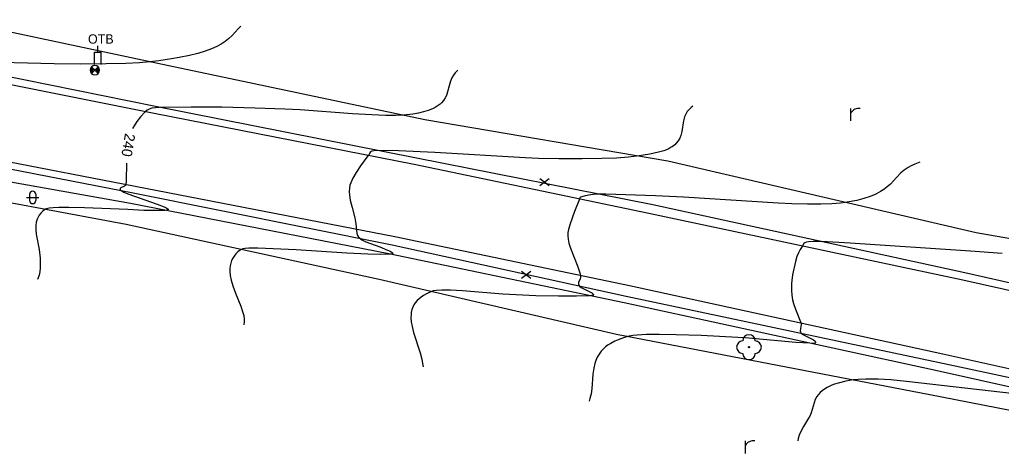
# Model space of a CAD drawing. Extents: x -593772 to -592667, y -1183541 to -1183371.
# Drawn here: x -593321.2 to -593242.3, y -1183436.1 to -1183401.2 of the extents above; entities that cross this region are included whole.
import ezdxf

# ---------------------------------------------------------------- set-up
doc = ezdxf.new("R2010")
doc.units = 0
for name, color, linetype in [('bez obruby', 7, 'Continuous'), ('hlavni vrstevnice', 7, 'Continuous'), ('popis ploch', 7, 'Continuous'), ('Statni bodove pole', 7, 'Continuous'), ('svisle dopravni znaceni', 7, 'Continuous'), ('terenni hrany', 7, 'Continuous'), ('vrstevnice', 7, 'Continuous'), ('zelen', 7, 'Continuous')]:
    doc.layers.add(name, color=color, linetype=linetype)

msp = doc.modelspace()

# ---------------------------------------------------------------- linework, layer by layer
at = {"layer": 'bez obruby'}
for p, q in [((-593310.39, -1183408.78), (-593327.76, -1183405.29)), ((-593289.5, -1183412.86), (-593310.39, -1183408.78)), ((-593311.94, -1183414.64), (-593328.65, -1183411.38)), ((-593270.63, -1183416.8), (-593289.5, -1183412.86)), ((-593291.05, -1183418.69), (-593311.94, -1183414.64)), ((-593245.4, -1183422.16), (-593270.63, -1183416.8)), ((-593272.2, -1183422.61), (-593291.05, -1183418.69)), ((-593247, -1183428.11), (-593272.2, -1183422.61)), ((-593226.44, -1183426.4), (-593245.4, -1183422.16)), ((-593227.63, -1183432.42), (-593247, -1183428.11))]:
    msp.add_line(p, q, dxfattribs=at)
at = {"layer": 'hlavni vrstevnice'}
for points in [[(-593285.982, -1183405.292), (-593286.206, -1183405.515), (-593286.352, -1183405.702), (-593286.466, -1183405.902), (-593286.579, -1183406.177), (-593286.681, -1183406.534), (-593286.808, -1183407.037), (-593286.906, -1183407.318), (-593287.004, -1183407.52), (-593287.133, -1183407.717), (-593287.291, -1183407.901), (-593287.42, -1183408.018), (-593287.645, -1183408.18), (-593287.822, -1183408.284), (-593288.022, -1183408.382), (-593288.382, -1183408.522), (-593288.748, -1183408.635), (-593289.158, -1183408.732), (-593289.621, -1183408.812), (-593290.362, -1183408.893), (-593290.981, -1183408.924), (-593291.776, -1183408.925), (-593292.914, -1183408.887), (-593294.455, -1183408.796), (-593298.67, -1183408.481), (-593299.901, -1183408.411), (-593302.272, -1183408.329), (-593304.97, -1183408.272), (-593307.424, -1183408.255), (-593309.976, -1183408.284), (-593310.301, -1183408.304), (-593310.598, -1183408.348), (-593310.808, -1183408.411), (-593310.953, -1183408.489), (-593311.146, -1183408.662), (-593311.487, -1183409.03), (-593311.787, -1183409.405), (-593312.017, -1183409.751), (-593312.141, -1183409.978)], [(-593312.62, -1183412.761), (-593312.649, -1183414.159), (-593312.669, -1183414.504), (-593312.698, -1183414.553), (-593312.797, -1183414.616), (-593313.076, -1183414.741), (-593313.133, -1183414.794), (-593313.144, -1183414.838), (-593313.121, -1183414.889), (-593313.055, -1183414.949), (-593312.841, -1183415.077), (-593312.524, -1183415.211), (-593310.152, -1183416.043), (-593309.597, -1183416.265), (-593309.391, -1183416.369), (-593309.307, -1183416.431), (-593309.282, -1183416.467), (-593309.285, -1183416.496), (-593309.316, -1183416.52), (-593309.41, -1183416.544), (-593309.511, -1183416.553), (-593310.49, -1183416.573), (-593311.236, -1183416.551), (-593312.526, -1183416.476), (-593315.997, -1183416.337), (-593317.267, -1183416.31), (-593318.053, -1183416.316), (-593318.531, -1183416.34), (-593318.842, -1183416.375), (-593319.046, -1183416.419), (-593319.156, -1183416.463), (-593319.376, -1183416.636), (-593319.515, -1183416.778), (-593319.63, -1183416.927), (-593319.724, -1183417.084), (-593319.798, -1183417.247), (-593319.873, -1183417.503), (-593319.909, -1183417.776), (-593319.912, -1183418.064), (-593319.873, -1183418.462), (-593319.656, -1183419.684), (-593319.575, -1183420.38), (-593319.553, -1183420.864), (-593319.563, -1183421.177), (-593319.596, -1183421.475), (-593319.656, -1183421.767), (-593319.77, -1183422.111)]]:
    msp.add_lwpolyline(points, dxfattribs=at)
at = {"layer": 'popis ploch'}
for p, q in [((-593254.39, -1183409.37), (-593254.39, -1183408.37)), ((-593320.66, -1183415.51), (-593319.66, -1183415.51)), ((-593320.41, -1183415.26), (-593320.41, -1183415.76)), ((-593319.91, -1183415.26), (-593319.91, -1183415.76)), ((-593262.87, -1183436.07), (-593262.87, -1183435.07))]:
    msp.add_line(p, q, dxfattribs=at)
for centre, radius, start, end in [((-593253.753, -1183409.107), 0.746, 81.32683, 148.70696), ((-593320.161, -1183415.26), 0.25, 0, 180), ((-593320.161, -1183415.76), 0.25, 180, 0), ((-593262.233, -1183435.808), 0.746, 81.32683, 148.70696)]:
    msp.add_arc(centre, radius, start, end, dxfattribs=at)
at = {"layer": 'Statni bodove pole'}
for p, q in [((-593315.425, -1183405.015), (-593315.16, -1183405.28)), ((-593315.16, -1183405.28), (-593315.425, -1183405.545)), ((-593314.895, -1183405.015), (-593315.16, -1183405.28)), ((-593315.16, -1183405.28), (-593314.895, -1183405.545))]:
    msp.add_line(p, q, dxfattribs=at)
for points in [[(-593315.19, -1183404.83), (-593315.19, -1183403.83), (-593314.69, -1183403.83), (-593314.69, -1183404.83)], [(-593314.94, -1183403.83), (-593314.94, -1183403.33)]]:
    msp.add_lwpolyline(points, dxfattribs=at)
for radius, start, end in [(0.374, 135, 225), (0.304, 135, 225), (0.376, 45, 135), (0.234, 135, 225), (0.164, 135, 225), (0.0944, 135, 225), (0.0244, 135, 225), (0.0244, 315, 45), (0.0944, 315, 45), (0.164, 315, 45), (0.234, 315, 45), (0.304, 315, 45), (0.374, 315, 45), (0.375, 225, 315)]:
    msp.add_arc((-593315.16, -1183405.28), radius, start, end, dxfattribs=at)
at = {"layer": 'svisle dopravni znaceni'}
for p, q in [((-593279.405, -1183414.561), (-593278.655, -1183413.998)), ((-593279.405, -1183413.998), (-593278.655, -1183414.561)), ((-593280.875, -1183421.991), (-593280.125, -1183421.428)), ((-593280.875, -1183421.428), (-593280.125, -1183421.991))]:
    msp.add_line(p, q, dxfattribs=at)
at = {"layer": 'terenni hrany'}
for p, q in [((-593309.21, -1183404.93), (-593326.71, -1183401.23)), ((-593310.28, -1183408.21), (-593327.54, -1183404.73)), ((-593288.63, -1183409.29), (-593309.21, -1183404.93)), ((-593289.3, -1183412.36), (-593310.28, -1183408.21)), ((-593269.12, -1183412.6), (-593288.63, -1183409.29)), ((-593312.1, -1183415.16), (-593328.71, -1183411.97)), ((-593270.31, -1183416.11), (-593289.3, -1183412.36)), ((-593312.31, -1183416.01), (-593328.81, -1183413.04)), ((-593244.32, -1183418.35), (-593269.12, -1183412.6)), ((-593312.66, -1183417.69), (-593328.27, -1183414.78)), ((-593291.28, -1183419.35), (-593312.1, -1183415.16)), ((-593291.53, -1183420.03), (-593312.31, -1183416.01)), ((-593245.24, -1183421.57), (-593270.31, -1183416.11)), ((-593292.31, -1183422.1), (-593312.66, -1183417.69)), ((-593225.65, -1183421.68), (-593244.32, -1183418.35)), ((-593272.46, -1183423.48), (-593291.28, -1183419.35)), ((-593272.62, -1183423.97), (-593291.53, -1183420.03)), ((-593226.34, -1183425.83), (-593245.24, -1183421.57)), ((-593273.23, -1183426.52), (-593292.31, -1183422.1)), ((-593247.27, -1183428.81), (-593272.46, -1183423.48)), ((-593247.47, -1183429.43), (-593272.62, -1183423.97)), ((-593248.06, -1183431.37), (-593273.23, -1183426.52)), ((-593227.72, -1183432.99), (-593247.27, -1183428.81)), ((-593227.84, -1183433.83), (-593247.47, -1183429.43)), ((-593228.15, -1183435.26), (-593248.06, -1183431.37))]:
    msp.add_line(p, q, dxfattribs=at)
at = {"layer": 'vrstevnice'}
for points in [[(-593303.436, -1183401.765), (-593303.659, -1183401.972), (-593304.129, -1183402.493), (-593304.427, -1183402.772), (-593304.7, -1183402.986), (-593305.009, -1183403.191), (-593305.358, -1183403.383), (-593305.782, -1183403.576), (-593306.288, -1183403.765), (-593306.89, -1183403.946), (-593307.551, -1183404.108), (-593308.392, -1183404.277), (-593309.012, -1183404.384), (-593310.02, -1183404.535), (-593310.745, -1183404.622), (-593311.579, -1183404.695), (-593312.679, -1183404.753), (-593314.253, -1183404.792), (-593316.359, -1183404.8), (-593318.428, -1183404.782), (-593324.873, -1183404.632)], [(-593267.106, -1183408.193), (-593267.243, -1183408.294), (-593267.381, -1183408.415), (-593267.546, -1183408.608), (-593267.672, -1183408.819), (-593267.763, -1183409.039), (-593267.844, -1183409.347), (-593267.985, -1183410.219), (-593268.065, -1183410.527), (-593268.154, -1183410.747), (-593268.274, -1183410.96), (-593268.428, -1183411.157), (-593268.555, -1183411.282), (-593268.752, -1183411.435), (-593268.831, -1183411.486), (-593269.092, -1183411.623), (-593269.445, -1183411.765), (-593269.861, -1183411.888), (-593270.55, -1183412.04), (-593271.409, -1183412.181), (-593272.266, -1183412.28), (-593273.242, -1183412.348), (-593274.418, -1183412.395), (-593275.986, -1183412.422), (-593277.879, -1183412.412), (-593279.508, -1183412.372), (-593280.579, -1183412.329), (-593287.849, -1183411.915), (-593290.757, -1183411.765), (-593292.439, -1183411.743), (-593292.742, -1183411.762), (-593292.91, -1183411.798), (-593293.01, -1183411.849), (-593293.065, -1183411.919), (-593293.118, -1183412.053), (-593293.219, -1183412.167), (-593293.806, -1183412.965), (-593294.163, -1183413.506), (-593294.424, -1183413.966), (-593294.6, -1183414.343), (-593294.663, -1183414.531), (-593294.708, -1183414.775), (-593294.72, -1183415.028), (-593294.699, -1183415.34), (-593294.635, -1183415.735), (-593294.494, -1183416.317), (-593294.278, -1183417.142), (-593294.191, -1183417.626), (-593294.117, -1183418.374), (-593294.073, -1183418.513), (-593293.989, -1183418.649), (-593293.816, -1183418.844), (-593293.709, -1183418.917), (-593293.382, -1183419.067), (-593292.272, -1183419.488), (-593291.638, -1183419.737), (-593291.442, -1183419.826), (-593291.268, -1183419.93), (-593291.22, -1183419.978), (-593291.215, -1183420.016), (-593291.252, -1183420.044), (-593291.389, -1183420.067), (-593291.581, -1183420.079), (-593292.191, -1183420.091), (-593293.214, -1183420.068), (-593294.912, -1183419.979), (-593298.994, -1183419.72), (-593302.08, -1183419.585), (-593302.783, -1183419.584), (-593303.098, -1183419.605), (-593303.264, -1183419.631), (-593303.415, -1183419.683), (-593303.674, -1183419.885), (-593303.837, -1183420.048), (-593303.975, -1183420.219), (-593304.088, -1183420.399), (-593304.178, -1183420.588), (-593304.244, -1183420.786), (-593304.288, -1183420.993), (-593304.311, -1183421.209), (-593304.312, -1183421.432), (-593304.28, -1183421.772), (-593304.205, -1183422.15), (-593304.07, -1183422.62), (-593303.852, -1183423.201), (-593303.433, -1183424.234), (-593303.288, -1183424.666), (-593303.205, -1183424.994), (-593303.164, -1183425.295), (-593303.16, -1183425.49), (-593303.186, -1183425.734)], [(-593248.844, -1183412.684), (-593249.25, -1183412.835), (-593249.54, -1183412.967), (-593249.796, -1183413.111), (-593250.106, -1183413.322), (-593250.373, -1183413.546), (-593250.725, -1183413.899), (-593251.225, -1183414.433), (-593251.475, -1183414.663), (-593251.759, -1183414.88), (-593252.017, -1183415.04), (-593252.396, -1183415.236), (-593252.844, -1183415.424), (-593253.35, -1183415.595), (-593253.923, -1183415.747), (-593254.703, -1183415.904), (-593255.226, -1183415.977), (-593255.937, -1183416.033), (-593256.813, -1183416.063), (-593257.887, -1183416.064), (-593259.152, -1183416.031), (-593260.248, -1183415.978), (-593267.863, -1183415.49), (-593270.113, -1183415.375), (-593274.086, -1183415.258), (-593274.638, -1183415.257), (-593275.122, -1183415.279), (-593275.495, -1183415.327), (-593275.823, -1183415.405), (-593276.128, -1183415.5), (-593276.178, -1183415.534), (-593276.206, -1183415.643), (-593276.6, -1183416.634), (-593276.952, -1183417.638), (-593277.087, -1183418.079), (-593277.137, -1183418.331), (-593277.153, -1183418.594), (-593277.131, -1183418.858), (-593277.063, -1183419.188), (-593276.941, -1183419.584), (-593276.342, -1183421.1), (-593276.191, -1183421.556), (-593276.126, -1183421.805), (-593276.121, -1183421.915), (-593276.155, -1183422.047), (-593276.28, -1183422.343), (-593276.298, -1183422.493), (-593276.267, -1183422.572), (-593276.195, -1183422.661), (-593276.067, -1183422.752), (-593275.222, -1183423.187), (-593275.103, -1183423.276), (-593275.081, -1183423.316), (-593275.089, -1183423.341), (-593275.108, -1183423.354), (-593275.22, -1183423.389), (-593275.419, -1183423.407), (-593276.461, -1183423.438), (-593277.902, -1183423.441), (-593279.716, -1183423.405), (-593281.294, -1183423.343), (-593282.373, -1183423.28), (-593285.618, -1183423.022), (-593286.578, -1183422.971), (-593287.264, -1183422.962), (-593287.718, -1183422.985), (-593287.976, -1183423.021), (-593288.107, -1183423.06), (-593288.506, -1183423.249), (-593288.74, -1183423.383), (-593288.936, -1183423.513), (-593289.112, -1183423.649), (-593289.265, -1183423.793), (-593289.425, -1183423.987), (-593289.525, -1183424.141), (-593289.617, -1183424.33), (-593289.685, -1183424.527), (-593289.734, -1183424.759), (-593289.755, -1183424.946), (-593289.759, -1183425.168), (-593289.732, -1183425.505), (-593289.668, -1183425.876), (-593289.548, -1183426.354), (-593289.023, -1183427.996), (-593288.89, -1183428.497), (-593288.822, -1183428.849), (-593288.787, -1183429.131)], [(-593242.232, -1183420.02), (-593244.774, -1183419.835), (-593254.46, -1183419.177), (-593256.756, -1183419.064), (-593257.433, -1183419.055), (-593257.797, -1183419.075), (-593257.976, -1183419.108), (-593258.095, -1183419.157), (-593258.168, -1183419.216), (-593258.308, -1183419.452), (-593258.466, -1183419.683), (-593258.617, -1183419.97), (-593258.734, -1183420.266), (-593258.851, -1183420.671), (-593259.082, -1183421.717), (-593259.147, -1183422.172), (-593259.164, -1183422.43), (-593259.175, -1183422.997), (-593259.153, -1183423.367), (-593259.098, -1183423.728), (-593259.023, -1183424.023), (-593258.861, -1183424.482), (-593258.401, -1183425.627), (-593258.387, -1183425.719), (-593258.451, -1183426.036), (-593258.468, -1183426.234), (-593258.448, -1183426.316), (-593258.39, -1183426.407), (-593258.31, -1183426.484), (-593258.141, -1183426.588), (-593257.407, -1183426.952), (-593257.26, -1183427.052), (-593257.233, -1183427.102), (-593257.253, -1183427.186), (-593257.304, -1183427.218), (-593257.418, -1183427.236), (-593257.705, -1183427.23), (-593258.822, -1183427.159), (-593262.893, -1183426.8), (-593263.478, -1183426.762), (-593266.433, -1183426.61), (-593268.434, -1183426.537), (-593269.82, -1183426.515), (-593270.832, -1183426.528), (-593271.57, -1183426.569), (-593271.936, -1183426.611), (-593272.351, -1183426.693), (-593272.676, -1183426.795), (-593273.11, -1183426.951), (-593273.366, -1183427.061), (-593273.701, -1183427.238), (-593273.903, -1183427.365), (-593274.114, -1183427.523), (-593274.318, -1183427.706), (-593274.458, -1183427.855), (-593274.641, -1183428.095), (-593274.784, -1183428.338), (-593274.899, -1183428.598), (-593274.987, -1183428.865), (-593275.07, -1183429.238), (-593275.132, -1183429.717), (-593275.227, -1183430.893), (-593275.283, -1183431.276), (-593275.368, -1183431.651), (-593275.435, -1183431.891)], [(-593241.234, -1183431.29), (-593249.932, -1183430.288), (-593251.178, -1183430.168), (-593252.2, -1183430.108), (-593253.203, -1183430.105), (-593253.806, -1183430.133), (-593254.205, -1183430.173), (-593254.807, -1183430.276), (-593255.306, -1183430.393), (-593255.719, -1183430.519), (-593255.938, -1183430.6), (-593256.304, -1183430.773), (-593256.522, -1183430.904), (-593256.711, -1183431.043), (-593256.872, -1183431.19), (-593257.008, -1183431.344), (-593257.121, -1183431.505), (-593257.256, -1183431.755), (-593257.361, -1183432.018), (-593257.601, -1183432.824), (-593257.709, -1183433.086), (-593257.803, -1183433.254), (-593258.217, -1183433.922), (-593258.397, -1183434.263), (-593258.545, -1183434.614), (-593258.63, -1183434.884), (-593258.67, -1183435.07)]]:
    msp.add_lwpolyline(points, dxfattribs=at)
at = {"layer": 'zelen'}
msp.add_circle((-593262.59, -1183427.54), 0.05, dxfattribs=at)
for centre, start, end in [((-593262.59, -1183427.04), 0, 180), ((-593263.09, -1183427.54), 90, 270), ((-593262.09, -1183427.54), 270, 90), ((-593262.59, -1183428.04), 180, 0)]:
    msp.add_arc(centre, 0.5, start, end, dxfattribs=at)

# ---------------------------------------------------------------- texts
at = {"layer": 'hlavni vrstevnice'}
msp.add_text('240', height=0.8351, rotation=260.65052, dxfattribs=at).set_placement((-593312.737, -1183410.321))
at = {"layer": 'Statni bodove pole'}
msp.add_text('OTB', height=0.75, dxfattribs=at).set_placement((-593315.717, -1183403.16))

doc.saveas('drawing.dxf')
